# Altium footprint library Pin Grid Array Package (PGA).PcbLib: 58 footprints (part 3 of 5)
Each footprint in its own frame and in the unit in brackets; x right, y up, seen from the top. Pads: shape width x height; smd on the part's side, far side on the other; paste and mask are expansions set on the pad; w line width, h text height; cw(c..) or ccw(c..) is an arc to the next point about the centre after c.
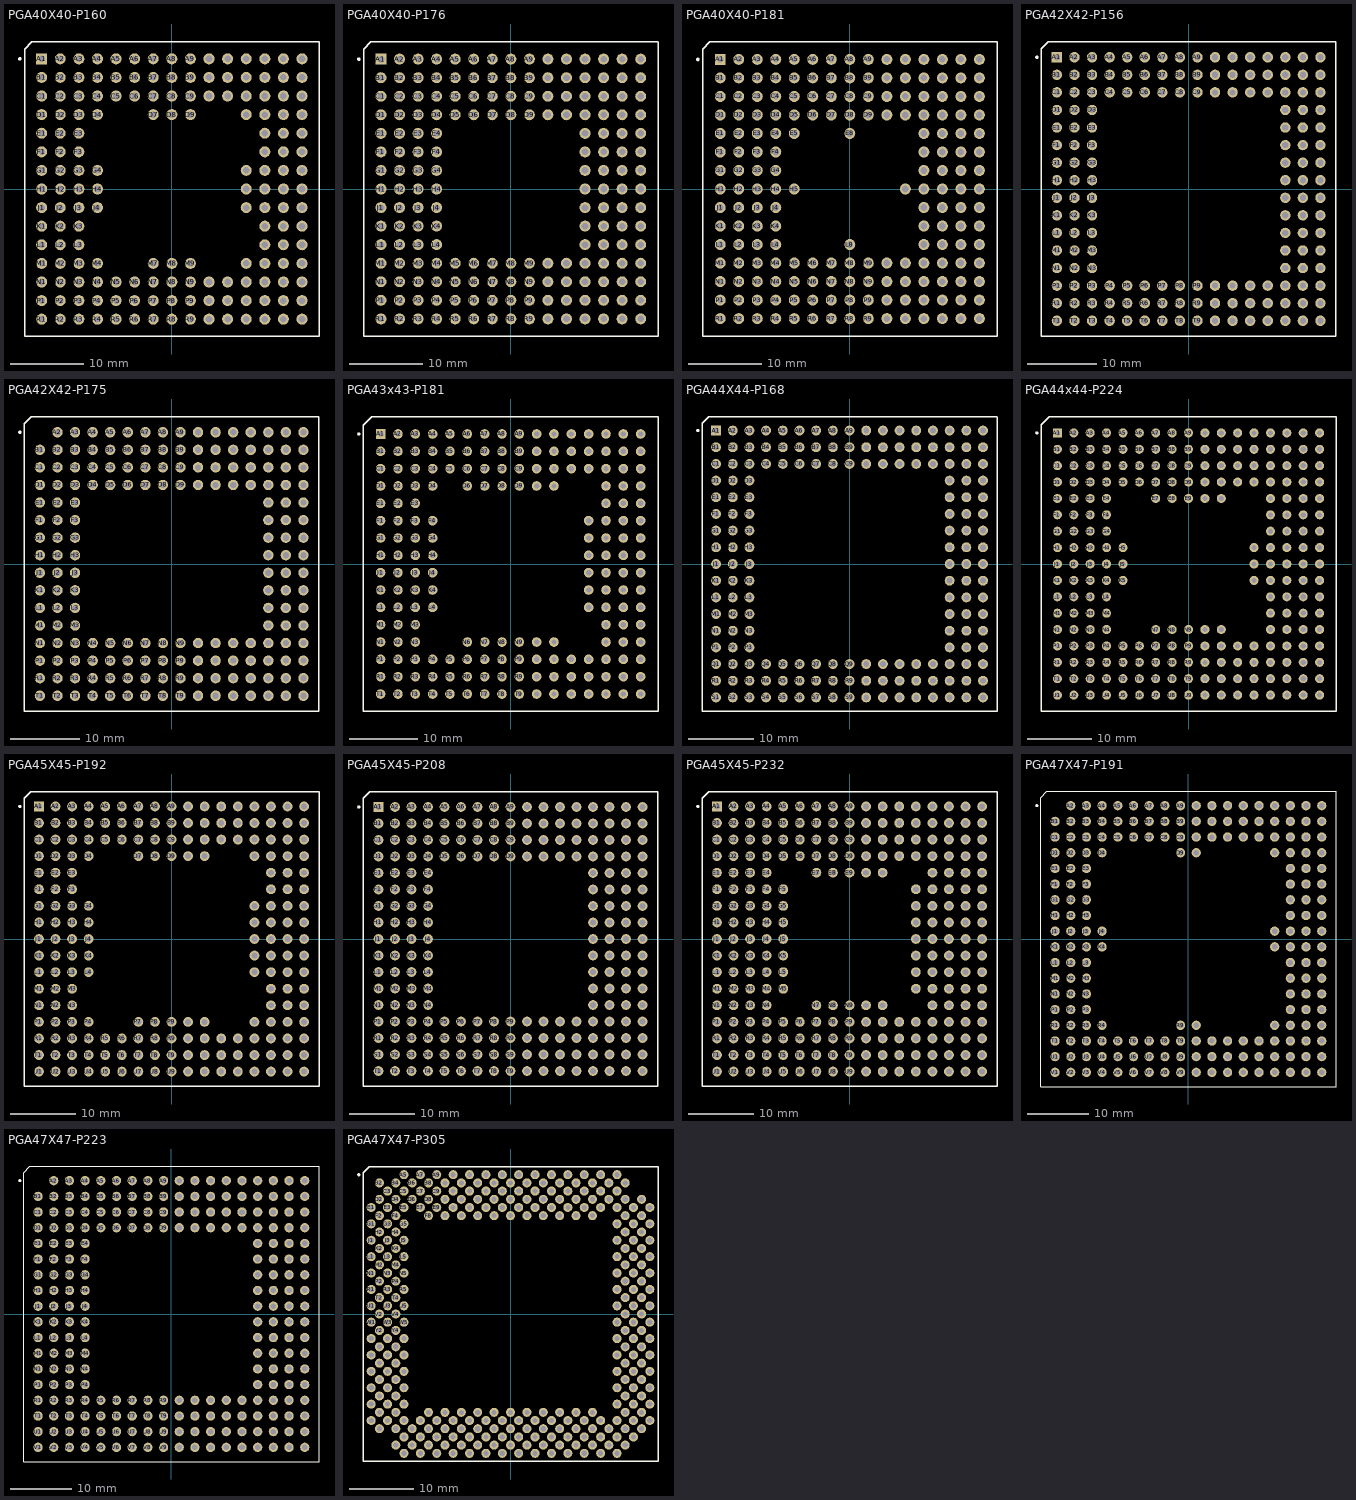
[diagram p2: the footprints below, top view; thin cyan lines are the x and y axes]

## PGA40X40-P160 [mm]
pads (160):
  rect 1.5x1.5 hole 0.9: A1(-17.78,17.78)
  round 1.5 hole 0.9: A2(-15.24,17.78) A3(-12.7,17.78) A4(-10.16,17.78) A5(-7.62,17.78) A6(-5.08,17.78) A7(-2.54,17.78) A8(0,17.78) A9(2.54,17.78) A10(5.08,17.78) A11(7.62,17.78) A12(10.16,17.78) A13(12.7,17.78) A14(15.24,17.78) A15(17.78,17.78) B1(-17.78,15.24) B2(-15.24,15.24) B3(-12.7,15.24) B4(-10.16,15.24) B5(-7.62,15.24) B6(-5.08,15.24) B7(-2.54,15.24) B8(0,15.24) B9(2.54,15.24) B10(5.08,15.24) B11(7.62,15.24) B12(10.16,15.24) B13(12.7,15.24) B14(15.24,15.24) B15(17.78,15.24) C1(-17.78,12.7) C2(-15.24,12.7) C3(-12.7,12.7) C4(-10.16,12.7) C5(-7.62,12.7) C6(-5.08,12.7) C7(-2.54,12.7) C8(0,12.7) C9(2.54,12.7) C10(5.08,12.7) C11(7.62,12.7) C12(10.16,12.7) C13(12.7,12.7) C14(15.24,12.7) C15(17.78,12.7) D1(-17.78,10.16) D2(-15.24,10.16) D3(-12.7,10.16) D4(-10.16,10.16) D7(-2.54,10.16) D8(0,10.16) D9(2.54,10.16) D12(10.16,10.16) D13(12.7,10.16) D14(15.24,10.16) D15(17.78,10.16) E1(-17.78,7.62) E2(-15.24,7.62) E3(-12.7,7.62) E13(12.7,7.62) E14(15.24,7.62) E15(17.78,7.62) F1(-17.78,5.08) F2(-15.24,5.08) F3(-12.7,5.08) F13(12.7,5.08) F14(15.24,5.08) F15(17.78,5.08) G1(-17.78,2.54) G2(-15.24,2.54) G3(-12.7,2.54) G4(-10.16,2.54) G12(10.16,2.54) G13(12.7,2.54) G14(15.24,2.54) G15(17.78,2.54) H1(-17.78,0) H2(-15.24,0) H3(-12.7,0) H4(-10.16,0) H12(10.16,0) H13(12.7,0) H14(15.24,0) H15(17.78,0) J1(-17.78,-2.54) J2(-15.24,-2.54) J3(-12.7,-2.54) J4(-10.16,-2.54) J12(10.16,-2.54) J13(12.7,-2.54) J14(15.24,-2.54) J15(17.78,-2.54) K1(-17.78,-5.08) K2(-15.24,-5.08) K3(-12.7,-5.08) K13(12.7,-5.08) K14(15.24,-5.08) K15(17.78,-5.08) L1(-17.78,-7.62) L2(-15.24,-7.62) L3(-12.7,-7.62) L13(12.7,-7.62) L14(15.24,-7.62) L15(17.78,-7.62) M1(-17.78,-10.16) M2(-15.24,-10.16) M3(-12.7,-10.16) M4(-10.16,-10.16) M7(-2.54,-10.16) M8(0,-10.16) M9(2.54,-10.16) M12(10.16,-10.16) M13(12.7,-10.16) M14(15.24,-10.16) M15(17.78,-10.16) N1(-17.78,-12.7) N2(-15.24,-12.7) N3(-12.7,-12.7) N4(-10.16,-12.7) N5(-7.62,-12.7) N6(-5.08,-12.7) N7(-2.54,-12.7) N8(0,-12.7) N9(2.54,-12.7) N10(5.08,-12.7) N11(7.62,-12.7) N12(10.16,-12.7) N13(12.7,-12.7) N14(15.24,-12.7) N15(17.78,-12.7) P1(-17.78,-15.24) P2(-15.24,-15.24) P3(-12.7,-15.24) P4(-10.16,-15.24) P5(-7.62,-15.24) P6(-5.08,-15.24) P7(-2.54,-15.24) P8(0,-15.24) P9(2.54,-15.24) P10(5.08,-15.24) P11(7.62,-15.24) P12(10.16,-15.24) P13(12.7,-15.24) P14(15.24,-15.24) P15(17.78,-15.24) R1(-17.78,-17.78) R2(-15.24,-17.78) R3(-12.7,-17.78) R4(-10.16,-17.78) R5(-7.62,-17.78) R6(-5.08,-17.78) R7(-2.54,-17.78) R8(0,-17.78) R9(2.54,-17.78) R10(5.08,-17.78) R11(7.62,-17.78) R12(10.16,-17.78) R13(12.7,-17.78) R14(15.24,-17.78) R15(17.78,-17.78)
Top Overlay:
  circle w0.25: c-20.75,17.78 r0.125
  lines w0.2: -20.1,-20.1 20.1,-20.1 20.1,20.1 -19.1,20.1 -20.1,19.1 -20.1,-20.1

## PGA40X40-P176 [mm]
pads (176):
  rect 1.5x1.5 hole 0.9: A1(-17.78,17.78)
  round 1.5 hole 0.9: A2(-15.24,17.78) A3(-12.7,17.78) A4(-10.16,17.78) A5(-7.62,17.78) A6(-5.08,17.78) A7(-2.54,17.78) A8(0,17.78) A9(2.54,17.78) A10(5.08,17.78) A11(7.62,17.78) A12(10.16,17.78) A13(12.7,17.78) A14(15.24,17.78) A15(17.78,17.78) B1(-17.78,15.24) B2(-15.24,15.24) B3(-12.7,15.24) B4(-10.16,15.24) B5(-7.62,15.24) B6(-5.08,15.24) B7(-2.54,15.24) B8(0,15.24) B9(2.54,15.24) B10(5.08,15.24) B11(7.62,15.24) B12(10.16,15.24) B13(12.7,15.24) B14(15.24,15.24) B15(17.78,15.24) C1(-17.78,12.7) C2(-15.24,12.7) C3(-12.7,12.7) C4(-10.16,12.7) C5(-7.62,12.7) C6(-5.08,12.7) C7(-2.54,12.7) C8(0,12.7) C9(2.54,12.7) C10(5.08,12.7) C11(7.62,12.7) C12(10.16,12.7) C13(12.7,12.7) C14(15.24,12.7) C15(17.78,12.7) D1(-17.78,10.16) D2(-15.24,10.16) D3(-12.7,10.16) D4(-10.16,10.16) D5(-7.62,10.16) D6(-5.08,10.16) D7(-2.54,10.16) D8(0,10.16) D9(2.54,10.16) D10(5.08,10.16) D11(7.62,10.16) D12(10.16,10.16) D13(12.7,10.16) D14(15.24,10.16) D15(17.78,10.16) E1(-17.78,7.62) E2(-15.24,7.62) E3(-12.7,7.62) E4(-10.16,7.62) E12(10.16,7.62) E13(12.7,7.62) E14(15.24,7.62) E15(17.78,7.62) F1(-17.78,5.08) F2(-15.24,5.08) F3(-12.7,5.08) F4(-10.16,5.08) F12(10.16,5.08) F13(12.7,5.08) F14(15.24,5.08) F15(17.78,5.08) G1(-17.78,2.54) G2(-15.24,2.54) G3(-12.7,2.54) G4(-10.16,2.54) G12(10.16,2.54) G13(12.7,2.54) G14(15.24,2.54) G15(17.78,2.54) H1(-17.78,0) H2(-15.24,0) H3(-12.7,0) H4(-10.16,0) H12(10.16,0) H13(12.7,0) H14(15.24,0) H15(17.78,0) J1(-17.78,-2.54) J2(-15.24,-2.54) J3(-12.7,-2.54) J4(-10.16,-2.54) J12(10.16,-2.54) J13(12.7,-2.54) J14(15.24,-2.54) J15(17.78,-2.54) K1(-17.78,-5.08) K2(-15.24,-5.08) K3(-12.7,-5.08) K4(-10.16,-5.08) K12(10.16,-5.08) K13(12.7,-5.08) K14(15.24,-5.08) K15(17.78,-5.08) L1(-17.78,-7.62) L2(-15.24,-7.62) L3(-12.7,-7.62) L4(-10.16,-7.62) L12(10.16,-7.62) L13(12.7,-7.62) L14(15.24,-7.62) L15(17.78,-7.62) M1(-17.78,-10.16) M2(-15.24,-10.16) M3(-12.7,-10.16) M4(-10.16,-10.16) M5(-7.62,-10.16) M6(-5.08,-10.16) M7(-2.54,-10.16) M8(0,-10.16) M9(2.54,-10.16) M10(5.08,-10.16) M11(7.62,-10.16) M12(10.16,-10.16) M13(12.7,-10.16) M14(15.24,-10.16) M15(17.78,-10.16) N1(-17.78,-12.7) N2(-15.24,-12.7) N3(-12.7,-12.7) N4(-10.16,-12.7) N5(-7.62,-12.7) N6(-5.08,-12.7) N7(-2.54,-12.7) N8(0,-12.7) N9(2.54,-12.7) N10(5.08,-12.7) N11(7.62,-12.7) N12(10.16,-12.7) N13(12.7,-12.7) N14(15.24,-12.7) N15(17.78,-12.7) P1(-17.78,-15.24) P2(-15.24,-15.24) P3(-12.7,-15.24) P4(-10.16,-15.24) P5(-7.62,-15.24) P6(-5.08,-15.24) P7(-2.54,-15.24) P8(0,-15.24) P9(2.54,-15.24) P10(5.08,-15.24) P11(7.62,-15.24) P12(10.16,-15.24) P13(12.7,-15.24) P14(15.24,-15.24) P15(17.78,-15.24) R1(-17.78,-17.78) R2(-15.24,-17.78) R3(-12.7,-17.78) R4(-10.16,-17.78) R5(-7.62,-17.78) R6(-5.08,-17.78) R7(-2.54,-17.78) R8(0,-17.78) R9(2.54,-17.78) R10(5.08,-17.78) R11(7.62,-17.78) R12(10.16,-17.78) R13(12.7,-17.78) R14(15.24,-17.78) R15(17.78,-17.78)
Top Overlay:
  circle w0.25: c-20.8,17.78 r0.125
  lines w0.2: -20.15,-20.15 20.15,-20.15 20.15,20.15 -19.15,20.15 -20.15,19.15 -20.15,-20.15

## PGA40X40-P181 [mm]
pads (181):
  rect 1.5x1.5 hole 0.9: A1(-17.78,17.78)
  round 1.5 hole 0.9: A2(-15.24,17.78) A3(-12.7,17.78) A4(-10.16,17.78) A5(-7.62,17.78) A6(-5.08,17.78) A7(-2.54,17.78) A8(0,17.78) A9(2.54,17.78) A10(5.08,17.78) A11(7.62,17.78) A12(10.16,17.78) A13(12.7,17.78) A14(15.24,17.78) A15(17.78,17.78) B1(-17.78,15.24) B2(-15.24,15.24) B3(-12.7,15.24) B4(-10.16,15.24) B5(-7.62,15.24) B6(-5.08,15.24) B7(-2.54,15.24) B8(0,15.24) B9(2.54,15.24) B10(5.08,15.24) B11(7.62,15.24) B12(10.16,15.24) B13(12.7,15.24) B14(15.24,15.24) B15(17.78,15.24) C1(-17.78,12.7) C2(-15.24,12.7) C3(-12.7,12.7) C4(-10.16,12.7) C5(-7.62,12.7) C6(-5.08,12.7) C7(-2.54,12.7) C8(0,12.7) C9(2.54,12.7) C10(5.08,12.7) C11(7.62,12.7) C12(10.16,12.7) C13(12.7,12.7) C14(15.24,12.7) C15(17.78,12.7) D1(-17.78,10.16) D2(-15.24,10.16) D3(-12.7,10.16) D4(-10.16,10.16) D5(-7.62,10.16) D6(-5.08,10.16) D7(-2.54,10.16) D8(0,10.16) D9(2.54,10.16) D10(5.08,10.16) D11(7.62,10.16) D12(10.16,10.16) D13(12.7,10.16) D14(15.24,10.16) D15(17.78,10.16) E1(-17.78,7.62) E2(-15.24,7.62) E3(-12.7,7.62) E4(-10.16,7.62) E5(-7.62,7.62) E8(0,7.62) E12(10.16,7.62) E13(12.7,7.62) E14(15.24,7.62) E15(17.78,7.62) F1(-17.78,5.08) F2(-15.24,5.08) F3(-12.7,5.08) F4(-10.16,5.08) F12(10.16,5.08) F13(12.7,5.08) F14(15.24,5.08) F15(17.78,5.08) G1(-17.78,2.54) G2(-15.24,2.54) G3(-12.7,2.54) G4(-10.16,2.54) G12(10.16,2.54) G13(12.7,2.54) G14(15.24,2.54) G15(17.78,2.54) H1(-17.78,0) H2(-15.24,0) H3(-12.7,0) H4(-10.16,0) H5(-7.62,0) H11(7.62,0) H12(10.16,0) H13(12.7,0) H14(15.24,0) H15(17.78,0) J1(-17.78,-2.54) J2(-15.24,-2.54) J3(-12.7,-2.54) J4(-10.16,-2.54) J12(10.16,-2.54) J13(12.7,-2.54) J14(15.24,-2.54) J15(17.78,-2.54) K1(-17.78,-5.08) K2(-15.24,-5.08) K3(-12.7,-5.08) K4(-10.16,-5.08) K12(10.16,-5.08) K13(12.7,-5.08) K14(15.24,-5.08) K15(17.78,-5.08) L1(-17.78,-7.62) L2(-15.24,-7.62) L3(-12.7,-7.62) L4(-10.16,-7.62) L8(0,-7.62) L12(10.16,-7.62) L13(12.7,-7.62) L14(15.24,-7.62) L15(17.78,-7.62) M1(-17.78,-10.16) M2(-15.24,-10.16) M3(-12.7,-10.16) M4(-10.16,-10.16) M5(-7.62,-10.16) M6(-5.08,-10.16) M7(-2.54,-10.16) M8(0,-10.16) M9(2.54,-10.16) M10(5.08,-10.16) M11(7.62,-10.16) M12(10.16,-10.16) M13(12.7,-10.16) M14(15.24,-10.16) M15(17.78,-10.16) N1(-17.78,-12.7) N2(-15.24,-12.7) N3(-12.7,-12.7) N4(-10.16,-12.7) N5(-7.62,-12.7) N6(-5.08,-12.7) N7(-2.54,-12.7) N8(0,-12.7) N9(2.54,-12.7) N10(5.08,-12.7) N11(7.62,-12.7) N12(10.16,-12.7) N13(12.7,-12.7) N14(15.24,-12.7) N15(17.78,-12.7) P1(-17.78,-15.24) P2(-15.24,-15.24) P3(-12.7,-15.24) P4(-10.16,-15.24) P5(-7.62,-15.24) P6(-5.08,-15.24) P7(-2.54,-15.24) P8(0,-15.24) P9(2.54,-15.24) P10(5.08,-15.24) P11(7.62,-15.24) P12(10.16,-15.24) P13(12.7,-15.24) P14(15.24,-15.24) P15(17.78,-15.24) R1(-17.78,-17.78) R2(-15.24,-17.78) R3(-12.7,-17.78) R4(-10.16,-17.78) R5(-7.62,-17.78) R6(-5.08,-17.78) R7(-2.54,-17.78) R8(0,-17.78) R9(2.54,-17.78) R10(5.08,-17.78) R11(7.62,-17.78) R12(10.16,-17.78) R13(12.7,-17.78) R14(15.24,-17.78) R15(17.78,-17.78)
Top Overlay:
  circle w0.25: c-20.85,17.78 r0.125
  lines w0.2: -20.2,-20.2 -20.2,19.2 -19.2,20.2 20.2,20.2 20.2,-20.2 -20.2,-20.2

## PGA42X42-P156 [mm]
pads (156):
  rect 1.5x1.5 hole 0.9: A1(-19.05,19.05)
  round 1.5 hole 0.9: A2(-16.51,19.05) A3(-13.97,19.05) A4(-11.43,19.05) A5(-8.89,19.05) A6(-6.35,19.05) A7(-3.81,19.05) A8(-1.27,19.05) A9(1.27,19.05) A10(3.81,19.05) A11(6.35,19.05) A12(8.89,19.05) A13(11.43,19.05) A14(13.97,19.05) A15(16.51,19.05) A16(19.05,19.05) B1(-19.05,16.51) B2(-16.51,16.51) B3(-13.97,16.51) B4(-11.43,16.51) B5(-8.89,16.51) B6(-6.35,16.51) B7(-3.81,16.51) B8(-1.27,16.51) B9(1.27,16.51) B10(3.81,16.51) B11(6.35,16.51) B12(8.89,16.51) B13(11.43,16.51) B14(13.97,16.51) B15(16.51,16.51) B16(19.05,16.51) C1(-19.05,13.97) C2(-16.51,13.97) C3(-13.97,13.97) C4(-11.43,13.97) C5(-8.89,13.97) C6(-6.35,13.97) C7(-3.81,13.97) C8(-1.27,13.97) C9(1.27,13.97) C10(3.81,13.97) C11(6.35,13.97) C12(8.89,13.97) C13(11.43,13.97) C14(13.97,13.97) C15(16.51,13.97) C16(19.05,13.97) D1(-19.05,11.43) D2(-16.51,11.43) D3(-13.97,11.43) D14(13.97,11.43) D15(16.51,11.43) D16(19.05,11.43) E1(-19.05,8.89) E2(-16.51,8.89) E3(-13.97,8.89) E14(13.97,8.89) E15(16.51,8.89) E16(19.05,8.89) F1(-19.05,6.35) F2(-16.51,6.35) F3(-13.97,6.35) F14(13.97,6.35) F15(16.51,6.35) F16(19.05,6.35) G1(-19.05,3.81) G2(-16.51,3.81) G3(-13.97,3.81) G14(13.97,3.81) G15(16.51,3.81) G16(19.05,3.81) H1(-19.05,1.27) H2(-16.51,1.27) H3(-13.97,1.27) H14(13.97,1.27) H15(16.51,1.27) H16(19.05,1.27) J1(-19.05,-1.27) J2(-16.51,-1.27) J3(-13.97,-1.27) J14(13.97,-1.27) J15(16.51,-1.27) J16(19.05,-1.27) K1(-19.05,-3.81) K2(-16.51,-3.81) K3(-13.97,-3.81) K14(13.97,-3.81) K15(16.51,-3.81) K16(19.05,-3.81) L1(-19.05,-6.35) L2(-16.51,-6.35) L3(-13.97,-6.35) L14(13.97,-6.35) L15(16.51,-6.35) L16(19.05,-6.35) M1(-19.05,-8.89) M2(-16.51,-8.89) M3(-13.97,-8.89) M14(13.97,-8.89) M15(16.51,-8.89) M16(19.05,-8.89) N1(-19.05,-11.43) N2(-16.51,-11.43) N3(-13.97,-11.43) N14(13.97,-11.43) N15(16.51,-11.43) N16(19.05,-11.43) P1(-19.05,-13.97) P2(-16.51,-13.97) P3(-13.97,-13.97) P4(-11.43,-13.97) P5(-8.89,-13.97) P6(-6.35,-13.97) P7(-3.81,-13.97) P8(-1.27,-13.97) P9(1.27,-13.97) P10(3.81,-13.97) P11(6.35,-13.97) P12(8.89,-13.97) P13(11.43,-13.97) P14(13.97,-13.97) P15(16.51,-13.97) P16(19.05,-13.97) R1(-19.05,-16.51) R2(-16.51,-16.51) R3(-13.97,-16.51) R4(-11.43,-16.51) R5(-8.89,-16.51) R6(-6.35,-16.51) R7(-3.81,-16.51) R8(-1.27,-16.51) R9(1.27,-16.51) R10(3.81,-16.51) R11(6.35,-16.51) R12(8.89,-16.51) R13(11.43,-16.51) R14(13.97,-16.51) R15(16.51,-16.51) R16(19.05,-16.51) T1(-19.05,-19.05) T2(-16.51,-19.05) T3(-13.97,-19.05) T4(-11.43,-19.05) T5(-8.89,-19.05) T6(-6.35,-19.05) T7(-3.81,-19.05) T8(-1.27,-19.05) T9(1.27,-19.05) T10(3.81,-19.05) T11(6.35,-19.05) T12(8.89,-19.05) T13(11.43,-19.05) T14(13.97,-19.05) T15(16.51,-19.05) T16(19.05,-19.05)
Top Overlay:
  circle w0.25: c-21.95,19.05 r0.125
  lines w0.2: -21.3,-21.3 -21.3,20.3 -20.3,21.3 21.3,21.3 21.3,-21.3 -21.3,-21.3

## PGA42X42-P175 [mm]
pads (175):
  round 1.5 hole 0.9: A2(-16.51,19.05) A3(-13.97,19.05) A4(-11.43,19.05) A5(-8.89,19.05) A6(-6.35,19.05) A7(-3.81,19.05) A8(-1.27,19.05) A9(1.27,19.05) A10(3.81,19.05) A11(6.35,19.05) A12(8.89,19.05) A13(11.43,19.05) A14(13.97,19.05) A15(16.51,19.05) A16(19.05,19.05) B1(-19.05,16.51) B2(-16.51,16.51) B3(-13.97,16.51) B4(-11.43,16.51) B5(-8.89,16.51) B6(-6.35,16.51) B7(-3.81,16.51) B8(-1.27,16.51) B9(1.27,16.51) B10(3.81,16.51) B11(6.35,16.51) B12(8.89,16.51) B13(11.43,16.51) B14(13.97,16.51) B15(16.51,16.51) B16(19.05,16.51) C1(-19.05,13.97) C2(-16.51,13.97) C3(-13.97,13.97) C4(-11.43,13.97) C5(-8.89,13.97) C6(-6.35,13.97) C7(-3.81,13.97) C8(-1.27,13.97) C9(1.27,13.97) C10(3.81,13.97) C11(6.35,13.97) C12(8.89,13.97) C13(11.43,13.97) C14(13.97,13.97) C15(16.51,13.97) C16(19.05,13.97) D1(-19.05,11.43) D2(-16.51,11.43) D3(-13.97,11.43) D4(-11.43,11.43) D5(-8.89,11.43) D6(-6.35,11.43) D7(-3.81,11.43) D8(-1.27,11.43) D9(1.27,11.43) D10(3.81,11.43) D11(6.35,11.43) D12(8.89,11.43) D13(11.43,11.43) D14(13.97,11.43) D15(16.51,11.43) D16(19.05,11.43) E1(-19.05,8.89) E2(-16.51,8.89) E3(-13.97,8.89) E14(13.97,8.89) E15(16.51,8.89) E16(19.05,8.89) F1(-19.05,6.35) F2(-16.51,6.35) F3(-13.97,6.35) F14(13.97,6.35) F15(16.51,6.35) F16(19.05,6.35) G1(-19.05,3.81) G2(-16.51,3.81) G3(-13.97,3.81) G14(13.97,3.81) G15(16.51,3.81) G16(19.05,3.81) H1(-19.05,1.27) H2(-16.51,1.27) H3(-13.97,1.27) H14(13.97,1.27) H15(16.51,1.27) H16(19.05,1.27) J1(-19.05,-1.27) J2(-16.51,-1.27) J3(-13.97,-1.27) J14(13.97,-1.27) J15(16.51,-1.27) J16(19.05,-1.27) K1(-19.05,-3.81) K2(-16.51,-3.81) K3(-13.97,-3.81) K14(13.97,-3.81) K15(16.51,-3.81) K16(19.05,-3.81) L1(-19.05,-6.35) L2(-16.51,-6.35) L3(-13.97,-6.35) L14(13.97,-6.35) L15(16.51,-6.35) L16(19.05,-6.35) M1(-19.05,-8.89) M2(-16.51,-8.89) M3(-13.97,-8.89) M14(13.97,-8.89) M15(16.51,-8.89) M16(19.05,-8.89) N1(-19.05,-11.43) N2(-16.51,-11.43) N3(-13.97,-11.43) N4(-11.43,-11.43) N5(-8.89,-11.43) N6(-6.35,-11.43) N7(-3.81,-11.43) N8(-1.27,-11.43) N9(1.27,-11.43) N10(3.81,-11.43) N11(6.35,-11.43) N12(8.89,-11.43) N13(11.43,-11.43) N14(13.97,-11.43) N15(16.51,-11.43) N16(19.05,-11.43) P1(-19.05,-13.97) P2(-16.51,-13.97) P3(-13.97,-13.97) P4(-11.43,-13.97) P5(-8.89,-13.97) P6(-6.35,-13.97) P7(-3.81,-13.97) P8(-1.27,-13.97) P9(1.27,-13.97) P10(3.81,-13.97) P11(6.35,-13.97) P12(8.89,-13.97) P13(11.43,-13.97) P14(13.97,-13.97) P15(16.51,-13.97) P16(19.05,-13.97) R1(-19.05,-16.51) R2(-16.51,-16.51) R3(-13.97,-16.51) R4(-11.43,-16.51) R5(-8.89,-16.51) R6(-6.35,-16.51) R7(-3.81,-16.51) R8(-1.27,-16.51) R9(1.27,-16.51) R10(3.81,-16.51) R11(6.35,-16.51) R12(8.89,-16.51) R13(11.43,-16.51) R14(13.97,-16.51) R15(16.51,-16.51) R16(19.05,-16.51) T1(-19.05,-19.05) T2(-16.51,-19.05) T3(-13.97,-19.05) T4(-11.43,-19.05) T5(-8.89,-19.05) T6(-6.35,-19.05) T7(-3.81,-19.05) T8(-1.27,-19.05) T9(1.27,-19.05) T10(3.81,-19.05) T11(6.35,-19.05) T12(8.89,-19.05) T13(11.43,-19.05) T14(13.97,-19.05) T15(16.51,-19.05) T16(19.05,-19.05)
Top Overlay:
  circle w0.25: c-21.95,19.05 r0.125
  lines w0.2: -21.3,-21.3 21.3,-21.3 21.3,21.3 -20.3,21.3 -21.3,20.3 -21.3,-21.3

## PGA43x43-P181 [mm]
pads (181):
  rect 1.4x1.4 hole 0.8: A1(-19.05,19.05)
  round 1.4 hole 0.8: A2(-16.51,19.05) A3(-13.97,19.05) A4(-11.43,19.05) A5(-8.89,19.05) A6(-6.35,19.05) A7(-3.81,19.05) A8(-1.27,19.05) A9(1.27,19.05) A10(3.81,19.05) A11(6.35,19.05) A12(8.89,19.05) A13(11.43,19.05) A14(13.97,19.05) A15(16.51,19.05) A16(19.05,19.05) B1(-19.05,16.51) B2(-16.51,16.51) B3(-13.97,16.51) B4(-11.43,16.51) B5(-8.89,16.51) B6(-6.35,16.51) B7(-3.81,16.51) B8(-1.27,16.51) B9(1.27,16.51) B10(3.81,16.51) B11(6.35,16.51) B12(8.89,16.51) B13(11.43,16.51) B14(13.97,16.51) B15(16.51,16.51) B16(19.05,16.51) C1(-19.05,13.97) C2(-16.51,13.97) C3(-13.97,13.97) C4(-11.43,13.97) C5(-8.89,13.97) C6(-6.35,13.97) C7(-3.81,13.97) C8(-1.27,13.97) C9(1.27,13.97) C10(3.81,13.97) C11(6.35,13.97) C12(8.89,13.97) C13(11.43,13.97) C14(13.97,13.97) C15(16.51,13.97) C16(19.05,13.97) D1(-19.05,11.43) D2(-16.51,11.43) D3(-13.97,11.43) D4(-11.43,11.43) D6(-6.35,11.43) D7(-3.81,11.43) D8(-1.27,11.43) D9(1.27,11.43) D10(3.81,11.43) D11(6.35,11.43) D14(13.97,11.43) D15(16.51,11.43) D16(19.05,11.43) E1(-19.05,8.89) E2(-16.51,8.89) E3(-13.97,8.89) E14(13.97,8.89) E15(16.51,8.89) E16(19.05,8.89) F1(-19.05,6.35) F2(-16.51,6.35) F3(-13.97,6.35) F4(-11.43,6.35) F13(11.43,6.35) F14(13.97,6.35) F15(16.51,6.35) F16(19.05,6.35) G1(-19.05,3.81) G2(-16.51,3.81) G3(-13.97,3.81) G4(-11.43,3.81) G13(11.43,3.81) G14(13.97,3.81) G15(16.51,3.81) G16(19.05,3.81) H1(-19.05,1.27) H2(-16.51,1.27) H3(-13.97,1.27) H4(-11.43,1.27) H13(11.43,1.27) H14(13.97,1.27) H15(16.51,1.27) H16(19.05,1.27) J1(-19.05,-1.27) J2(-16.51,-1.27) J3(-13.97,-1.27) J4(-11.43,-1.27) J13(11.43,-1.27) J14(13.97,-1.27) J15(16.51,-1.27) J16(19.05,-1.27) K1(-19.05,-3.81) K2(-16.51,-3.81) K3(-13.97,-3.81) K4(-11.43,-3.81) K13(11.43,-3.81) K14(13.97,-3.81) K15(16.51,-3.81) K16(19.05,-3.81) L1(-19.05,-6.35) L2(-16.51,-6.35) L3(-13.97,-6.35) L4(-11.43,-6.35) L13(11.43,-6.35) L14(13.97,-6.35) L15(16.51,-6.35) L16(19.05,-6.35) M1(-19.05,-8.89) M2(-16.51,-8.89) M3(-13.97,-8.89) M14(13.97,-8.89) M15(16.51,-8.89) M16(19.05,-8.89) N1(-19.05,-11.43) N2(-16.51,-11.43) N3(-13.97,-11.43) N6(-6.35,-11.43) N7(-3.81,-11.43) N8(-1.27,-11.43) N9(1.27,-11.43) N10(3.81,-11.43) N11(6.35,-11.43) N14(13.97,-11.43) N15(16.51,-11.43) N16(19.05,-11.43) P1(-19.05,-13.97) P2(-16.51,-13.97) P3(-13.97,-13.97) P4(-11.43,-13.97) P5(-8.89,-13.97) P6(-6.35,-13.97) P7(-3.81,-13.97) P8(-1.27,-13.97) P9(1.27,-13.97) P10(3.81,-13.97) P11(6.35,-13.97) P12(8.89,-13.97) P13(11.43,-13.97) P14(13.97,-13.97) P15(16.51,-13.97) P16(19.05,-13.97) R1(-19.05,-16.51) R2(-16.51,-16.51) R3(-13.97,-16.51) R4(-11.43,-16.51) R5(-8.89,-16.51) R6(-6.35,-16.51) R7(-3.81,-16.51) R8(-1.27,-16.51) R9(1.27,-16.51) R10(3.81,-16.51) R11(6.35,-16.51) R12(8.89,-16.51) R13(11.43,-16.51) R14(13.97,-16.51) R15(16.51,-16.51) R16(19.05,-16.51) T1(-19.05,-19.05) T2(-16.51,-19.05) T3(-13.97,-19.05) T4(-11.43,-19.05) T5(-8.89,-19.05) T6(-6.35,-19.05) T7(-3.81,-19.05) T8(-1.27,-19.05) T9(1.27,-19.05) T10(3.81,-19.05) T11(6.35,-19.05) T12(8.89,-19.05) T13(11.43,-19.05) T14(13.97,-19.05) T15(16.51,-19.05) T16(19.05,-19.05)
Top Overlay:
  circle w0.25: c-22.24,19.05 r0.125
  lines w0.2: -21.59,-21.59 21.59,-21.59 21.59,21.59 -20.32,21.59 -21.59,20.32 -21.59,-21.59

## PGA44X44-P168 [mm]
pads (168):
  rect 1.5x1.5 hole 0.9: A1(-20.32,20.32)
  round 1.5 hole 0.9: A2(-17.78,20.32) A3(-15.24,20.32) A4(-12.7,20.32) A5(-10.16,20.32) A6(-7.62,20.32) A7(-5.08,20.32) A8(-2.54,20.32) A9(0,20.32) A10(2.54,20.32) A11(5.08,20.32) A12(7.62,20.32) A13(10.16,20.32) A14(12.7,20.32) A15(15.24,20.32) A16(17.78,20.32) A17(20.32,20.32) B1(-20.32,17.78) B2(-17.78,17.78) B3(-15.24,17.78) B4(-12.7,17.78) B5(-10.16,17.78) B6(-7.62,17.78) B7(-5.08,17.78) B8(-2.54,17.78) B9(0,17.78) B10(2.54,17.78) B11(5.08,17.78) B12(7.62,17.78) B13(10.16,17.78) B14(12.7,17.78) B15(15.24,17.78) B16(17.78,17.78) B17(20.32,17.78) C1(-20.32,15.24) C2(-17.78,15.24) C3(-15.24,15.24) C4(-12.7,15.24) C5(-10.16,15.24) C6(-7.62,15.24) C7(-5.08,15.24) C8(-2.54,15.24) C9(0,15.24) C10(2.54,15.24) C11(5.08,15.24) C12(7.62,15.24) C13(10.16,15.24) C14(12.7,15.24) C15(15.24,15.24) C16(17.78,15.24) C17(20.32,15.24) D1(-20.32,12.7) D2(-17.78,12.7) D3(-15.24,12.7) D15(15.24,12.7) D16(17.78,12.7) D17(20.32,12.7) E1(-20.32,10.16) E2(-17.78,10.16) E3(-15.24,10.16) E15(15.24,10.16) E16(17.78,10.16) E17(20.32,10.16) F1(-20.32,7.62) F2(-17.78,7.62) F3(-15.24,7.62) F15(15.24,7.62) F16(17.78,7.62) F17(20.32,7.62) G1(-20.32,5.08) G2(-17.78,5.08) G3(-15.24,5.08) G15(15.24,5.08) G16(17.78,5.08) G17(20.32,5.08) H1(-20.32,2.54) H2(-17.78,2.54) H3(-15.24,2.54) H15(15.24,2.54) H16(17.78,2.54) H17(20.32,2.54) J1(-20.32,0) J2(-17.78,0) J3(-15.24,0) J15(15.24,0) J16(17.78,0) J17(20.32,0) K1(-20.32,-2.54) K2(-17.78,-2.54) K3(-15.24,-2.54) K15(15.24,-2.54) K16(17.78,-2.54) K17(20.32,-2.54) L1(-20.32,-5.08) L2(-17.78,-5.08) L3(-15.24,-5.08) L15(15.24,-5.08) L16(17.78,-5.08) L17(20.32,-5.08) M1(-20.32,-7.62) M2(-17.78,-7.62) M3(-15.24,-7.62) M15(15.24,-7.62) M16(17.78,-7.62) M17(20.32,-7.62) N1(-20.32,-10.16) N2(-17.78,-10.16) N3(-15.24,-10.16) N15(15.24,-10.16) N16(17.78,-10.16) N17(20.32,-10.16) P1(-20.32,-12.7) P2(-17.78,-12.7) P3(-15.24,-12.7) P15(15.24,-12.7) P16(17.78,-12.7) P17(20.32,-12.7) Q1(-20.32,-15.24) Q2(-17.78,-15.24) Q3(-15.24,-15.24) Q4(-12.7,-15.24) Q5(-10.16,-15.24) Q6(-7.62,-15.24) Q7(-5.08,-15.24) Q8(-2.54,-15.24) Q9(0,-15.24) Q10(2.54,-15.24) Q11(5.08,-15.24) Q12(7.62,-15.24) Q13(10.16,-15.24) Q14(12.7,-15.24) Q15(15.24,-15.24) Q16(17.78,-15.24) Q17(20.32,-15.24) R1(-20.32,-17.78) R2(-17.78,-17.78) R3(-15.24,-17.78) R4(-12.7,-17.78) R5(-10.16,-17.78) R6(-7.62,-17.78) R7(-5.08,-17.78) R8(-2.54,-17.78) R9(0,-17.78) R10(2.54,-17.78) R11(5.08,-17.78) R12(7.62,-17.78) R13(10.16,-17.78) R14(12.7,-17.78) R15(15.24,-17.78) R16(17.78,-17.78) R17(20.32,-17.78) S1(-20.32,-20.32) S2(-17.78,-20.32) S3(-15.24,-20.32) S4(-12.7,-20.32) S5(-10.16,-20.32) S6(-7.62,-20.32) S7(-5.08,-20.32) S8(-2.54,-20.32) S9(0,-20.32) S10(2.54,-20.32) S11(5.08,-20.32) S12(7.62,-20.32) S13(10.16,-20.32) S14(12.7,-20.32) S15(15.24,-20.32) S16(17.78,-20.32) S17(20.32,-20.32)
Top Overlay:
  circle w0.25: c-23.1,20.32 r0.125
  lines w0.2: -22.45,-22.45 -22.45,21.45 -21.45,22.45 22.45,22.45 22.45,-22.45 -22.45,-22.45

## PGA44x44-P224 [mm]
pads (224):
  rect 1.4x1.4 hole 0.8: A1(-20.32,20.32)
  round 1.4 hole 0.8: A2(-17.78,20.32) A3(-15.24,20.32) A4(-12.7,20.32) A5(-10.16,20.32) A6(-7.62,20.32) A7(-5.08,20.32) A8(-2.54,20.32) A9(0,20.32) A10(2.54,20.32) A11(5.08,20.32) A12(7.62,20.32) A13(10.16,20.32) A14(12.7,20.32) A15(15.24,20.32) A16(17.78,20.32) A17(20.32,20.32) B1(-20.32,17.78) B2(-17.78,17.78) B3(-15.24,17.78) B4(-12.7,17.78) B5(-10.16,17.78) B6(-7.62,17.78) B7(-5.08,17.78) B8(-2.54,17.78) B9(0,17.78) B10(2.54,17.78) B11(5.08,17.78) B12(7.62,17.78) B13(10.16,17.78) B14(12.7,17.78) B15(15.24,17.78) B16(17.78,17.78) B17(20.32,17.78) C1(-20.32,15.24) C2(-17.78,15.24) C3(-15.24,15.24) C4(-12.7,15.24) C5(-10.16,15.24) C6(-7.62,15.24) C7(-5.08,15.24) C8(-2.54,15.24) C9(0,15.24) C10(2.54,15.24) C11(5.08,15.24) C12(7.62,15.24) C13(10.16,15.24) C14(12.7,15.24) C15(15.24,15.24) C16(17.78,15.24) C17(20.32,15.24) D1(-20.32,12.7) D2(-17.78,12.7) D3(-15.24,12.7) D4(-12.7,12.7) D5(-10.16,12.7) D6(-7.62,12.7) D7(-5.08,12.7) D8(-2.54,12.7) D9(0,12.7) D10(2.54,12.7) D11(5.08,12.7) D12(7.62,12.7) D13(10.16,12.7) D14(12.7,12.7) D15(15.24,12.7) D16(17.78,12.7) D17(20.32,12.7) E1(-20.32,10.16) E2(-17.78,10.16) E3(-15.24,10.16) E4(-12.7,10.16) E7(-5.08,10.16) E8(-2.54,10.16) E9(0,10.16) E10(2.54,10.16) E11(5.08,10.16) E14(12.7,10.16) E15(15.24,10.16) E16(17.78,10.16) E17(20.32,10.16) F1(-20.32,7.62) F2(-17.78,7.62) F3(-15.24,7.62) F4(-12.7,7.62) F14(12.7,7.62) F15(15.24,7.62) F16(17.78,7.62) F17(20.32,7.62) G1(-20.32,5.08) G2(-17.78,5.08) G3(-15.24,5.08) G4(-12.7,5.08) G14(12.7,5.08) G15(15.24,5.08) G16(17.78,5.08) G17(20.32,5.08) H1(-20.32,2.54) H2(-17.78,2.54) H3(-15.24,2.54) H4(-12.7,2.54) H5(-10.16,2.54) H13(10.16,2.54) H14(12.7,2.54) H15(15.24,2.54) H16(17.78,2.54) H17(20.32,2.54) J1(-20.32,0) J2(-17.78,0) J3(-15.24,0) J4(-12.7,0) J5(-10.16,0) J13(10.16,0) J14(12.7,0) J15(15.24,0) J16(17.78,0) J17(20.32,0) K1(-20.32,-2.54) K2(-17.78,-2.54) K3(-15.24,-2.54) K4(-12.7,-2.54) K5(-10.16,-2.54) K13(10.16,-2.54) K14(12.7,-2.54) K15(15.24,-2.54) K16(17.78,-2.54) K17(20.32,-2.54) L1(-20.32,-5.08) L2(-17.78,-5.08) L3(-15.24,-5.08) L4(-12.7,-5.08) L14(12.7,-5.08) L15(15.24,-5.08) L16(17.78,-5.08) L17(20.32,-5.08) M1(-20.32,-7.62) M2(-17.78,-7.62) M3(-15.24,-7.62) M4(-12.7,-7.62) M14(12.7,-7.62) M15(15.24,-7.62) M16(17.78,-7.62) M17(20.32,-7.62) N1(-20.32,-10.16) N2(-17.78,-10.16) N3(-15.24,-10.16) N4(-12.7,-10.16) N7(-5.08,-10.16) N8(-2.54,-10.16) N9(0,-10.16) N10(2.54,-10.16) N11(5.08,-10.16) N14(12.7,-10.16) N15(15.24,-10.16) N16(17.78,-10.16) N17(20.32,-10.16) P1(-20.32,-12.7) P2(-17.78,-12.7) P3(-15.24,-12.7) P4(-12.7,-12.7) P5(-10.16,-12.7) P6(-7.62,-12.7) P7(-5.08,-12.7) P8(-2.54,-12.7) P9(0,-12.7) P10(2.54,-12.7) P11(5.08,-12.7) P12(7.62,-12.7) P13(10.16,-12.7) P14(12.7,-12.7) P15(15.24,-12.7) P16(17.78,-12.7) P17(20.32,-12.7) R1(-20.32,-15.24) R2(-17.78,-15.24) R3(-15.24,-15.24) R4(-12.7,-15.24) R5(-10.16,-15.24) R6(-7.62,-15.24) R7(-5.08,-15.24) R8(-2.54,-15.24) R9(0,-15.24) R10(2.54,-15.24) R11(5.08,-15.24) R12(7.62,-15.24) R13(10.16,-15.24) R14(12.7,-15.24) R15(15.24,-15.24) R16(17.78,-15.24) R17(20.32,-15.24) T1(-20.32,-17.78) T2(-17.78,-17.78) T3(-15.24,-17.78) T4(-12.7,-17.78) T5(-10.16,-17.78) T6(-7.62,-17.78) T7(-5.08,-17.78) T8(-2.54,-17.78) T9(0,-17.78) T10(2.54,-17.78) T11(5.08,-17.78) T12(7.62,-17.78) T13(10.16,-17.78) T14(12.7,-17.78) T15(15.24,-17.78) T16(17.78,-17.78) T17(20.32,-17.78) U1(-20.32,-20.32) U2(-17.78,-20.32) U3(-15.24,-20.32) U4(-12.7,-20.32) U5(-10.16,-20.32) U6(-7.62,-20.32) U7(-5.08,-20.32) U8(-2.54,-20.32) U9(0,-20.32) U10(2.54,-20.32) U11(5.08,-20.32) U12(7.62,-20.32) U13(10.16,-20.32) U14(12.7,-20.32) U15(15.24,-20.32) U16(17.78,-20.32) U17(20.32,-20.32)
Top Overlay:
  circle w0.25: c-23.51,20.32 r0.125
  lines w0.2: -22.86,-22.86 -22.86,21.59 -21.59,22.86 22.86,22.86 22.86,-22.86 -22.86,-22.86

## PGA45X45-P192 [mm]
pads (192):
  rect 1.5x1.5 hole 0.9: A1(-20.32,20.32)
  round 1.5 hole 0.9: A2(-17.78,20.32) A3(-15.24,20.32) A4(-12.7,20.32) A5(-10.16,20.32) A6(-7.62,20.32) A7(-5.08,20.32) A8(-2.54,20.32) A9(0,20.32) A10(2.54,20.32) A11(5.08,20.32) A12(7.62,20.32) A13(10.16,20.32) A14(12.7,20.32) A15(15.24,20.32) A16(17.78,20.32) A17(20.32,20.32) B1(-20.32,17.78) B2(-17.78,17.78) B3(-15.24,17.78) B4(-12.7,17.78) B5(-10.16,17.78) B6(-7.62,17.78) B7(-5.08,17.78) B8(-2.54,17.78) B9(0,17.78) B10(2.54,17.78) B11(5.08,17.78) B12(7.62,17.78) B13(10.16,17.78) B14(12.7,17.78) B15(15.24,17.78) B16(17.78,17.78) B17(20.32,17.78) C1(-20.32,15.24) C2(-17.78,15.24) C3(-15.24,15.24) C4(-12.7,15.24) C5(-10.16,15.24) C6(-7.62,15.24) C7(-5.08,15.24) C8(-2.54,15.24) C9(0,15.24) C10(2.54,15.24) C11(5.08,15.24) C12(7.62,15.24) C13(10.16,15.24) C14(12.7,15.24) C15(15.24,15.24) C16(17.78,15.24) C17(20.32,15.24) D1(-20.32,12.7) D2(-17.78,12.7) D3(-15.24,12.7) D4(-12.7,12.7) D7(-5.08,12.7) D8(-2.54,12.7) D9(0,12.7) D10(2.54,12.7) D11(5.08,12.7) D14(12.7,12.7) D15(15.24,12.7) D16(17.78,12.7) D17(20.32,12.7) E1(-20.32,10.16) E2(-17.78,10.16) E3(-15.24,10.16) E15(15.24,10.16) E16(17.78,10.16) E17(20.32,10.16) F1(-20.32,7.62) F2(-17.78,7.62) F3(-15.24,7.62) F15(15.24,7.62) F16(17.78,7.62) F17(20.32,7.62) G1(-20.32,5.08) G2(-17.78,5.08) G3(-15.24,5.08) G4(-12.7,5.08) G14(12.7,5.08) G15(15.24,5.08) G16(17.78,5.08) G17(20.32,5.08) H1(-20.32,2.54) H2(-17.78,2.54) H3(-15.24,2.54) H4(-12.7,2.54) H14(12.7,2.54) H15(15.24,2.54) H16(17.78,2.54) H17(20.32,2.54) J1(-20.32,0) J2(-17.78,0) J3(-15.24,0) J4(-12.7,0) J14(12.7,0) J15(15.24,0) J16(17.78,0) J17(20.32,0) K1(-20.32,-2.54) K2(-17.78,-2.54) K3(-15.24,-2.54) K4(-12.7,-2.54) K14(12.7,-2.54) K15(15.24,-2.54) K16(17.78,-2.54) K17(20.32,-2.54) L1(-20.32,-5.08) L2(-17.78,-5.08) L3(-15.24,-5.08) L4(-12.7,-5.08) L14(12.7,-5.08) L15(15.24,-5.08) L16(17.78,-5.08) L17(20.32,-5.08) M1(-20.32,-7.62) M2(-17.78,-7.62) M3(-15.24,-7.62) M15(15.24,-7.62) M16(17.78,-7.62) M17(20.32,-7.62) N1(-20.32,-10.16) N2(-17.78,-10.16) N3(-15.24,-10.16) N15(15.24,-10.16) N16(17.78,-10.16) N17(20.32,-10.16) P1(-20.32,-12.7) P2(-17.78,-12.7) P3(-15.24,-12.7) P4(-12.7,-12.7) P7(-5.08,-12.7) P8(-2.54,-12.7) P9(0,-12.7) P10(2.54,-12.7) P11(5.08,-12.7) P14(12.7,-12.7) P15(15.24,-12.7) P16(17.78,-12.7) P17(20.32,-12.7) R1(-20.32,-15.24) R2(-17.78,-15.24) R3(-15.24,-15.24) R4(-12.7,-15.24) R5(-10.16,-15.24) R6(-7.62,-15.24) R7(-5.08,-15.24) R8(-2.54,-15.24) R9(0,-15.24) R10(2.54,-15.24) R11(5.08,-15.24) R12(7.62,-15.24) R13(10.16,-15.24) R14(12.7,-15.24) R15(15.24,-15.24) R16(17.78,-15.24) R17(20.32,-15.24) T1(-20.32,-17.78) T2(-17.78,-17.78) T3(-15.24,-17.78) T4(-12.7,-17.78) T5(-10.16,-17.78) T6(-7.62,-17.78) T7(-5.08,-17.78) T8(-2.54,-17.78) T9(0,-17.78) T10(2.54,-17.78) T11(5.08,-17.78) T12(7.62,-17.78) T13(10.16,-17.78) T14(12.7,-17.78) T15(15.24,-17.78) T16(17.78,-17.78) T17(20.32,-17.78) U1(-20.32,-20.32) U2(-17.78,-20.32) U3(-15.24,-20.32) U4(-12.7,-20.32) U5(-10.16,-20.32) U6(-7.62,-20.32) U7(-5.08,-20.32) U8(-2.54,-20.32) U9(0,-20.32) U10(2.54,-20.32) U11(5.08,-20.32) U12(7.62,-20.32) U13(10.16,-20.32) U14(12.7,-20.32) U15(15.24,-20.32) U16(17.78,-20.32) U17(20.32,-20.32)
Top Overlay:
  circle w0.25: c-23.25,20.32 r0.125
  lines w0.2: -22.6,-22.6 -22.6,21.6 -21.6,22.6 22.6,22.6 22.6,-22.6 -22.6,-22.6

## PGA45X45-P208 [mm]
pads (208):
  rect 1.5x1.5 hole 0.9: A1(-20.32,20.32)
  round 1.5 hole 0.9: A2(-17.78,20.32) A3(-15.24,20.32) A4(-12.7,20.32) A5(-10.16,20.32) A6(-7.62,20.32) A7(-5.08,20.32) A8(-2.54,20.32) A9(0,20.32) A10(2.54,20.32) A11(5.08,20.32) A12(7.62,20.32) A13(10.16,20.32) A14(12.7,20.32) A15(15.24,20.32) A16(17.78,20.32) A17(20.32,20.32) B1(-20.32,17.78) B2(-17.78,17.78) B3(-15.24,17.78) B4(-12.7,17.78) B5(-10.16,17.78) B6(-7.62,17.78) B7(-5.08,17.78) B8(-2.54,17.78) B9(0,17.78) B10(2.54,17.78) B11(5.08,17.78) B12(7.62,17.78) B13(10.16,17.78) B14(12.7,17.78) B15(15.24,17.78) B16(17.78,17.78) B17(20.32,17.78) C1(-20.32,15.24) C2(-17.78,15.24) C3(-15.24,15.24) C4(-12.7,15.24) C5(-10.16,15.24) C6(-7.62,15.24) C7(-5.08,15.24) C8(-2.54,15.24) C9(0,15.24) C10(2.54,15.24) C11(5.08,15.24) C12(7.62,15.24) C13(10.16,15.24) C14(12.7,15.24) C15(15.24,15.24) C16(17.78,15.24) C17(20.32,15.24) D1(-20.32,12.7) D2(-17.78,12.7) D3(-15.24,12.7) D4(-12.7,12.7) D5(-10.16,12.7) D6(-7.62,12.7) D7(-5.08,12.7) D8(-2.54,12.7) D9(0,12.7) D10(2.54,12.7) D11(5.08,12.7) D12(7.62,12.7) D13(10.16,12.7) D14(12.7,12.7) D15(15.24,12.7) D16(17.78,12.7) D17(20.32,12.7) E1(-20.32,10.16) E2(-17.78,10.16) E3(-15.24,10.16) E4(-12.7,10.16) E14(12.7,10.16) E15(15.24,10.16) E16(17.78,10.16) E17(20.32,10.16) F1(-20.32,7.62) F2(-17.78,7.62) F3(-15.24,7.62) F4(-12.7,7.62) F14(12.7,7.62) F15(15.24,7.62) F16(17.78,7.62) F17(20.32,7.62) G1(-20.32,5.08) G2(-17.78,5.08) G3(-15.24,5.08) G4(-12.7,5.08) G14(12.7,5.08) G15(15.24,5.08) G16(17.78,5.08) G17(20.32,5.08) H1(-20.32,2.54) H2(-17.78,2.54) H3(-15.24,2.54) H4(-12.7,2.54) H14(12.7,2.54) H15(15.24,2.54) H16(17.78,2.54) H17(20.32,2.54) J1(-20.32,0) J2(-17.78,0) J3(-15.24,0) J4(-12.7,0) J14(12.7,0) J15(15.24,0) J16(17.78,0) J17(20.32,0) K1(-20.32,-2.54) K2(-17.78,-2.54) K3(-15.24,-2.54) K4(-12.7,-2.54) K14(12.7,-2.54) K15(15.24,-2.54) K16(17.78,-2.54) K17(20.32,-2.54) L1(-20.32,-5.08) L2(-17.78,-5.08) L3(-15.24,-5.08) L4(-12.7,-5.08) L14(12.7,-5.08) L15(15.24,-5.08) L16(17.78,-5.08) L17(20.32,-5.08) M1(-20.32,-7.62) M2(-17.78,-7.62) M3(-15.24,-7.62) M4(-12.7,-7.62) M14(12.7,-7.62) M15(15.24,-7.62) M16(17.78,-7.62) M17(20.32,-7.62) N1(-20.32,-10.16) N2(-17.78,-10.16) N3(-15.24,-10.16) N4(-12.7,-10.16) N14(12.7,-10.16) N15(15.24,-10.16) N16(17.78,-10.16) N17(20.32,-10.16) P1(-20.32,-12.7) P2(-17.78,-12.7) P3(-15.24,-12.7) P4(-12.7,-12.7) P5(-10.16,-12.7) P6(-7.62,-12.7) P7(-5.08,-12.7) P8(-2.54,-12.7) P9(0,-12.7) P10(2.54,-12.7) P11(5.08,-12.7) P12(7.62,-12.7) P13(10.16,-12.7) P14(12.7,-12.7) P15(15.24,-12.7) P16(17.78,-12.7) P17(20.32,-12.7) R1(-20.32,-15.24) R2(-17.78,-15.24) R3(-15.24,-15.24) R4(-12.7,-15.24) R5(-10.16,-15.24) R6(-7.62,-15.24) R7(-5.08,-15.24) R8(-2.54,-15.24) R9(0,-15.24) R10(2.54,-15.24) R11(5.08,-15.24) R12(7.62,-15.24) R13(10.16,-15.24) R14(12.7,-15.24) R15(15.24,-15.24) R16(17.78,-15.24) R17(20.32,-15.24) S1(-20.32,-17.78) S2(-17.78,-17.78) S3(-15.24,-17.78) S4(-12.7,-17.78) S5(-10.16,-17.78) S6(-7.62,-17.78) S7(-5.08,-17.78) S8(-2.54,-17.78) S9(0,-17.78) S10(2.54,-17.78) S11(5.08,-17.78) S12(7.62,-17.78) S13(10.16,-17.78) S14(12.7,-17.78) S15(15.24,-17.78) S16(17.78,-17.78) S17(20.32,-17.78) T1(-20.32,-20.32) T2(-17.78,-20.32) T3(-15.24,-20.32) T4(-12.7,-20.32) T5(-10.16,-20.32) T6(-7.62,-20.32) T7(-5.08,-20.32) T8(-2.54,-20.32) T9(0,-20.32) T10(2.54,-20.32) T11(5.08,-20.32) T12(7.62,-20.32) T13(10.16,-20.32) T14(12.7,-20.32) T15(15.24,-20.32) T16(17.78,-20.32) T17(20.32,-20.32)
Top Overlay:
  circle w0.25: c-23.35,20.32 r0.125
  lines w0.2: -22.7,-22.7 22.7,-22.7 22.7,22.7 -21.7,22.7 -22.7,21.7 -22.7,-22.7

## PGA45X45-P232 [mm]
pads (232):
  rect 1.5x1.5 hole 0.9: A1(-20.32,20.32)
  round 1.5 hole 0.9: A2(-17.78,20.32) A3(-15.24,20.32) A4(-12.7,20.32) A5(-10.16,20.32) A6(-7.62,20.32) A7(-5.08,20.32) A8(-2.54,20.32) A9(0,20.32) A10(2.54,20.32) A11(5.08,20.32) A12(7.62,20.32) A13(10.16,20.32) A14(12.7,20.32) A15(15.24,20.32) A16(17.78,20.32) A17(20.32,20.32) B1(-20.32,17.78) B2(-17.78,17.78) B3(-15.24,17.78) B4(-12.7,17.78) B5(-10.16,17.78) B6(-7.62,17.78) B7(-5.08,17.78) B8(-2.54,17.78) B9(0,17.78) B10(2.54,17.78) B11(5.08,17.78) B12(7.62,17.78) B13(10.16,17.78) B14(12.7,17.78) B15(15.24,17.78) B16(17.78,17.78) B17(20.32,17.78) C1(-20.32,15.24) C2(-17.78,15.24) C3(-15.24,15.24) C4(-12.7,15.24) C5(-10.16,15.24) C6(-7.62,15.24) C7(-5.08,15.24) C8(-2.54,15.24) C9(0,15.24) C10(2.54,15.24) C11(5.08,15.24) C12(7.62,15.24) C13(10.16,15.24) C14(12.7,15.24) C15(15.24,15.24) C16(17.78,15.24) C17(20.32,15.24) D1(-20.32,12.7) D2(-17.78,12.7) D3(-15.24,12.7) D4(-12.7,12.7) D5(-10.16,12.7) D6(-7.62,12.7) D7(-5.08,12.7) D8(-2.54,12.7) D9(0,12.7) D10(2.54,12.7) D11(5.08,12.7) D12(7.62,12.7) D13(10.16,12.7) D14(12.7,12.7) D15(15.24,12.7) D16(17.78,12.7) D17(20.32,12.7) E1(-20.32,10.16) E2(-17.78,10.16) E3(-15.24,10.16) E4(-12.7,10.16) E7(-5.08,10.16) E8(-2.54,10.16) E9(0,10.16) E10(2.54,10.16) E11(5.08,10.16) E14(12.7,10.16) E15(15.24,10.16) E16(17.78,10.16) E17(20.32,10.16) F1(-20.32,7.62) F2(-17.78,7.62) F3(-15.24,7.62) F4(-12.7,7.62) F5(-10.16,7.62) F13(10.16,7.62) F14(12.7,7.62) F15(15.24,7.62) F16(17.78,7.62) F17(20.32,7.62) G1(-20.32,5.08) G2(-17.78,5.08) G3(-15.24,5.08) G4(-12.7,5.08) G5(-10.16,5.08) G13(10.16,5.08) G14(12.7,5.08) G15(15.24,5.08) G16(17.78,5.08) G17(20.32,5.08) H1(-20.32,2.54) H2(-17.78,2.54) H3(-15.24,2.54) H4(-12.7,2.54) H5(-10.16,2.54) H13(10.16,2.54) H14(12.7,2.54) H15(15.24,2.54) H16(17.78,2.54) H17(20.32,2.54) J1(-20.32,0) J2(-17.78,0) J3(-15.24,0) J4(-12.7,0) J5(-10.16,0) J13(10.16,0) J14(12.7,0) J15(15.24,0) J16(17.78,0) J17(20.32,0) K1(-20.32,-2.54) K2(-17.78,-2.54) K3(-15.24,-2.54) K4(-12.7,-2.54) K5(-10.16,-2.54) K13(10.16,-2.54) K14(12.7,-2.54) K15(15.24,-2.54) K16(17.78,-2.54) K17(20.32,-2.54) L1(-20.32,-5.08) L2(-17.78,-5.08) L3(-15.24,-5.08) L4(-12.7,-5.08) L5(-10.16,-5.08) L13(10.16,-5.08) L14(12.7,-5.08) L15(15.24,-5.08) L16(17.78,-5.08) L17(20.32,-5.08) M1(-20.32,-7.62) M2(-17.78,-7.62) M3(-15.24,-7.62) M4(-12.7,-7.62) M5(-10.16,-7.62) M13(10.16,-7.62) M14(12.7,-7.62) M15(15.24,-7.62) M16(17.78,-7.62) M17(20.32,-7.62) N1(-20.32,-10.16) N2(-17.78,-10.16) N3(-15.24,-10.16) N4(-12.7,-10.16) N7(-5.08,-10.16) N8(-2.54,-10.16) N9(0,-10.16) N10(2.54,-10.16) N11(5.08,-10.16) N14(12.7,-10.16) N15(15.24,-10.16) N16(17.78,-10.16) N17(20.32,-10.16) P1(-20.32,-12.7) P2(-17.78,-12.7) P3(-15.24,-12.7) P4(-12.7,-12.7) P5(-10.16,-12.7) P6(-7.62,-12.7) P7(-5.08,-12.7) P8(-2.54,-12.7) P9(0,-12.7) P10(2.54,-12.7) P11(5.08,-12.7) P12(7.62,-12.7) P13(10.16,-12.7) P14(12.7,-12.7) P15(15.24,-12.7) P16(17.78,-12.7) P17(20.32,-12.7) R1(-20.32,-15.24) R2(-17.78,-15.24) R3(-15.24,-15.24) R4(-12.7,-15.24) R5(-10.16,-15.24) R6(-7.62,-15.24) R7(-5.08,-15.24) R8(-2.54,-15.24) R9(0,-15.24) R10(2.54,-15.24) R11(5.08,-15.24) R12(7.62,-15.24) R13(10.16,-15.24) R14(12.7,-15.24) R15(15.24,-15.24) R16(17.78,-15.24) R17(20.32,-15.24) T1(-20.32,-17.78) T2(-17.78,-17.78) T3(-15.24,-17.78) T4(-12.7,-17.78) T5(-10.16,-17.78) T6(-7.62,-17.78) T7(-5.08,-17.78) T8(-2.54,-17.78) T9(0,-17.78) T10(2.54,-17.78) T11(5.08,-17.78) T12(7.62,-17.78) T13(10.16,-17.78) T14(12.7,-17.78) T15(15.24,-17.78) T16(17.78,-17.78) T17(20.32,-17.78) U1(-20.32,-20.32) U2(-17.78,-20.32) U3(-15.24,-20.32) U4(-12.7,-20.32) U5(-10.16,-20.32) U6(-7.62,-20.32) U7(-5.08,-20.32) U8(-2.54,-20.32) U9(0,-20.32) U10(2.54,-20.32) U11(5.08,-20.32) U12(7.62,-20.32) U13(10.16,-20.32) U14(12.7,-20.32) U15(15.24,-20.32) U16(17.78,-20.32) U17(20.32,-20.32)
Top Overlay:
  circle w0.25: c-23.25,20.32 r0.125
  lines w0.2: -22.6,-22.6 -22.6,21.6 -21.6,22.6 22.6,22.6 22.6,-22.6 -22.6,-22.6

## PGA47X47-P191 [mm]
pads (191):
  round 1.5 hole 0.9: A2(-19.05,21.59) A3(-16.51,21.59) A4(-13.97,21.59) A5(-11.43,21.59) A6(-8.89,21.59) A7(-6.35,21.59) A8(-3.81,21.59) A9(-1.27,21.59) A10(1.27,21.59) A11(3.81,21.59) A12(6.35,21.59) A13(8.89,21.59) A14(11.43,21.59) A15(13.97,21.59) A16(16.51,21.59) A17(19.05,21.59) A18(21.59,21.59) B1(-21.59,19.05) B2(-19.05,19.05) B3(-16.51,19.05) B4(-13.97,19.05) B5(-11.43,19.05) B6(-8.89,19.05) B7(-6.35,19.05) B8(-3.81,19.05) B9(-1.27,19.05) B10(1.27,19.05) B11(3.81,19.05) B12(6.35,19.05) B13(8.89,19.05) B14(11.43,19.05) B15(13.97,19.05) B16(16.51,19.05) B17(19.05,19.05) B18(21.59,19.05) C1(-21.59,16.51) C2(-19.05,16.51) C3(-16.51,16.51) C4(-13.97,16.51) C5(-11.43,16.51) C6(-8.89,16.51) C7(-6.35,16.51) C8(-3.81,16.51) C9(-1.27,16.51) C10(1.27,16.51) C11(3.81,16.51) C12(6.35,16.51) C13(8.89,16.51) C14(11.43,16.51) C15(13.97,16.51) C16(16.51,16.51) C17(19.05,16.51) C18(21.59,16.51) D1(-21.59,13.97) D2(-19.05,13.97) D3(-16.51,13.97) D4(-13.97,13.97) D9(-1.27,13.97) D10(1.27,13.97) D15(13.97,13.97) D16(16.51,13.97) D17(19.05,13.97) D18(21.59,13.97) E1(-21.59,11.43) E2(-19.05,11.43) E3(-16.51,11.43) E16(16.51,11.43) E17(19.05,11.43) E18(21.59,11.43) F1(-21.59,8.89) F2(-19.05,8.89) F3(-16.51,8.89) F16(16.51,8.89) F17(19.05,8.89) F18(21.59,8.89) G1(-21.59,6.35) G2(-19.05,6.35) G3(-16.51,6.35) G16(16.51,6.35) G17(19.05,6.35) G18(21.59,6.35) H1(-21.59,3.81) H2(-19.05,3.81) H3(-16.51,3.81) H16(16.51,3.81) H17(19.05,3.81) H18(21.59,3.81) J1(-21.59,1.27) J2(-19.05,1.27) J3(-16.51,1.27) J4(-13.97,1.27) J15(13.97,1.27) J16(16.51,1.27) J17(19.05,1.27) J18(21.59,1.27) K1(-21.59,-1.27) K2(-19.05,-1.27) K3(-16.51,-1.27) K4(-13.97,-1.27) K15(13.97,-1.27) K16(16.51,-1.27) K17(19.05,-1.27) K18(21.59,-1.27) L1(-21.59,-3.81) L2(-19.05,-3.81) L3(-16.51,-3.81) L16(16.51,-3.81) L17(19.05,-3.81) L18(21.59,-3.81) M1(-21.59,-6.35) M2(-19.05,-6.35) M3(-16.51,-6.35) M16(16.51,-6.35) M17(19.05,-6.35) M18(21.59,-6.35) N1(-21.59,-8.89) N2(-19.05,-8.89) N3(-16.51,-8.89) N16(16.51,-8.89) N17(19.05,-8.89) N18(21.59,-8.89) P1(-21.59,-11.43) P2(-19.05,-11.43) P3(-16.51,-11.43) P16(16.51,-11.43) P17(19.05,-11.43) P18(21.59,-11.43) R1(-21.59,-13.97) R2(-19.05,-13.97) R3(-16.51,-13.97) R4(-13.97,-13.97) R9(-1.27,-13.97) R10(1.27,-13.97) R15(13.97,-13.97) R16(16.51,-13.97) R17(19.05,-13.97) R18(21.59,-13.97) T1(-21.59,-16.51) T2(-19.05,-16.51) T3(-16.51,-16.51) T4(-13.97,-16.51) T5(-11.43,-16.51) T6(-8.89,-16.51) T7(-6.35,-16.51) T8(-3.81,-16.51) T9(-1.27,-16.51) T10(1.27,-16.51) T11(3.81,-16.51) T12(6.35,-16.51) T13(8.89,-16.51) T14(11.43,-16.51) T15(13.97,-16.51) T16(16.51,-16.51) T17(19.05,-16.51) T18(21.59,-16.51) U1(-21.59,-19.05) U2(-19.05,-19.05) U3(-16.51,-19.05) U4(-13.97,-19.05) U5(-11.43,-19.05) U6(-8.89,-19.05) U7(-6.35,-19.05) U8(-3.81,-19.05) U9(-1.27,-19.05) U10(1.27,-19.05) U11(3.81,-19.05) U12(6.35,-19.05) U13(8.89,-19.05) U14(11.43,-19.05) U15(13.97,-19.05) U16(16.51,-19.05) U17(19.05,-19.05) U18(21.59,-19.05) V1(-21.59,-21.59) V2(-19.05,-21.59) V3(-16.51,-21.59) V4(-13.97,-21.59) V5(-11.43,-21.59) V6(-8.89,-21.59) V7(-6.35,-21.59) V8(-3.81,-21.59) V9(-1.27,-21.59) V10(1.27,-21.59) V11(3.81,-21.59) V12(6.35,-21.59) V13(8.89,-21.59) V14(11.43,-21.59) V15(13.97,-21.59) V16(16.51,-21.59) V17(19.05,-21.59) V18(21.59,-21.59)
Top Overlay:
  circle w0.25: c-24.55,21.59 r0.125
  lines w0.2: -23.9,-23.9 -23.9,22.9 -22.9,23.9 23.9,23.9 23.9,-23.9 -23.9,-23.9

## PGA47X47-P223 [mm]
pads (223):
  round 1.5 hole 0.9: A2(-19.05,21.59) A3(-16.51,21.59) A4(-13.97,21.59) A5(-11.43,21.59) A6(-8.89,21.59) A7(-6.35,21.59) A8(-3.81,21.59) A9(-1.27,21.59) A10(1.27,21.59) A11(3.81,21.59) A12(6.35,21.59) A13(8.89,21.59) A14(11.43,21.59) A15(13.97,21.59) A16(16.51,21.59) A17(19.05,21.59) A18(21.59,21.59) B1(-21.59,19.05) B2(-19.05,19.05) B3(-16.51,19.05) B4(-13.97,19.05) B5(-11.43,19.05) B6(-8.89,19.05) B7(-6.35,19.05) B8(-3.81,19.05) B9(-1.27,19.05) B10(1.27,19.05) B11(3.81,19.05) B12(6.35,19.05) B13(8.89,19.05) B14(11.43,19.05) B15(13.97,19.05) B16(16.51,19.05) B17(19.05,19.05) B18(21.59,19.05) C1(-21.59,16.51) C2(-19.05,16.51) C3(-16.51,16.51) C4(-13.97,16.51) C5(-11.43,16.51) C6(-8.89,16.51) C7(-6.35,16.51) C8(-3.81,16.51) C9(-1.27,16.51) C10(1.27,16.51) C11(3.81,16.51) C12(6.35,16.51) C13(8.89,16.51) C14(11.43,16.51) C15(13.97,16.51) C16(16.51,16.51) C17(19.05,16.51) C18(21.59,16.51) D1(-21.59,13.97) D2(-19.05,13.97) D3(-16.51,13.97) D4(-13.97,13.97) D5(-11.43,13.97) D6(-8.89,13.97) D7(-6.35,13.97) D8(-3.81,13.97) D9(-1.27,13.97) D10(1.27,13.97) D11(3.81,13.97) D12(6.35,13.97) D13(8.89,13.97) D14(11.43,13.97) D15(13.97,13.97) D16(16.51,13.97) D17(19.05,13.97) D18(21.59,13.97) E1(-21.59,11.43) E2(-19.05,11.43) E3(-16.51,11.43) E4(-13.97,11.43) E15(13.97,11.43) E16(16.51,11.43) E17(19.05,11.43) E18(21.59,11.43) F1(-21.59,8.89) F2(-19.05,8.89) F3(-16.51,8.89) F4(-13.97,8.89) F15(13.97,8.89) F16(16.51,8.89) F17(19.05,8.89) F18(21.59,8.89) G1(-21.59,6.35) G2(-19.05,6.35) G3(-16.51,6.35) G4(-13.97,6.35) G15(13.97,6.35) G16(16.51,6.35) G17(19.05,6.35) G18(21.59,6.35) H1(-21.59,3.81) H2(-19.05,3.81) H3(-16.51,3.81) H4(-13.97,3.81) H15(13.97,3.81) H16(16.51,3.81) H17(19.05,3.81) H18(21.59,3.81) J1(-21.59,1.27) J2(-19.05,1.27) J3(-16.51,1.27) J4(-13.97,1.27) J15(13.97,1.27) J16(16.51,1.27) J17(19.05,1.27) J18(21.59,1.27) K1(-21.59,-1.27) K2(-19.05,-1.27) K3(-16.51,-1.27) K4(-13.97,-1.27) K15(13.97,-1.27) K16(16.51,-1.27) K17(19.05,-1.27) K18(21.59,-1.27) L1(-21.59,-3.81) L2(-19.05,-3.81) L3(-16.51,-3.81) L4(-13.97,-3.81) L15(13.97,-3.81) L16(16.51,-3.81) L17(19.05,-3.81) L18(21.59,-3.81) M1(-21.59,-6.35) M2(-19.05,-6.35) M3(-16.51,-6.35) M4(-13.97,-6.35) M15(13.97,-6.35) M16(16.51,-6.35) M17(19.05,-6.35) M18(21.59,-6.35) N1(-21.59,-8.89) N2(-19.05,-8.89) N3(-16.51,-8.89) N4(-13.97,-8.89) N15(13.97,-8.89) N16(16.51,-8.89) N17(19.05,-8.89) N18(21.59,-8.89) P1(-21.59,-11.43) P2(-19.05,-11.43) P3(-16.51,-11.43) P4(-13.97,-11.43) P15(13.97,-11.43) P16(16.51,-11.43) P17(19.05,-11.43) P18(21.59,-11.43) R1(-21.59,-13.97) R2(-19.05,-13.97) R3(-16.51,-13.97) R4(-13.97,-13.97) R5(-11.43,-13.97) R6(-8.89,-13.97) R7(-6.35,-13.97) R8(-3.81,-13.97) R9(-1.27,-13.97) R10(1.27,-13.97) R11(3.81,-13.97) R12(6.35,-13.97) R13(8.89,-13.97) R14(11.43,-13.97) R15(13.97,-13.97) R16(16.51,-13.97) R17(19.05,-13.97) R18(21.59,-13.97) T1(-21.59,-16.51) T2(-19.05,-16.51) T3(-16.51,-16.51) T4(-13.97,-16.51) T5(-11.43,-16.51) T6(-8.89,-16.51) T7(-6.35,-16.51) T8(-3.81,-16.51) T9(-1.27,-16.51) T10(1.27,-16.51) T11(3.81,-16.51) T12(6.35,-16.51) T13(8.89,-16.51) T14(11.43,-16.51) T15(13.97,-16.51) T16(16.51,-16.51) T17(19.05,-16.51) T18(21.59,-16.51) U1(-21.59,-19.05) U2(-19.05,-19.05) U3(-16.51,-19.05) U4(-13.97,-19.05) U5(-11.43,-19.05) U6(-8.89,-19.05) U7(-6.35,-19.05) U8(-3.81,-19.05) U9(-1.27,-19.05) U10(1.27,-19.05) U11(3.81,-19.05) U12(6.35,-19.05) U13(8.89,-19.05) U14(11.43,-19.05) U15(13.97,-19.05) U16(16.51,-19.05) U17(19.05,-19.05) U18(21.59,-19.05) V1(-21.59,-21.59) V2(-19.05,-21.59) V3(-16.51,-21.59) V4(-13.97,-21.59) V5(-11.43,-21.59) V6(-8.89,-21.59) V7(-6.35,-21.59) V8(-3.81,-21.59) V9(-1.27,-21.59) V10(1.27,-21.59) V11(3.81,-21.59) V12(6.35,-21.59) V13(8.89,-21.59) V14(11.43,-21.59) V15(13.97,-21.59) V16(16.51,-21.59) V17(19.05,-21.59) V18(21.59,-21.59)
Top Overlay:
  circle w0.25: c-24.55,21.59 r0.125
  lines w0.2: -23.9,-23.9 23.9,-23.9 23.9,23.9 -22.9,23.9 -23.9,22.9 -23.9,-23.9

## PGA47X47-P305 [mm]
pads (305):
  round 1.4 hole 0.8: A5(-16.51,21.59) A7(-13.97,21.59) A9(-11.43,21.59) A11(-8.89,21.59) A13(-6.35,21.59) A15(-3.81,21.59) A17(-1.27,21.59) A19(1.27,21.59) A21(3.81,21.59) A23(6.35,21.59) A25(8.89,21.59) A27(11.43,21.59) A29(13.97,21.59) A31(16.51,21.59) AA1(-21.59,-3.81) AA3(-19.05,-3.81) AA5(-16.51,-3.81) AA31(16.51,-3.81) AA33(19.05,-3.81) AA35(21.59,-3.81) AB2(-20.32,-5.08) AB4(-17.78,-5.08) AB32(17.78,-5.08) AB34(20.32,-5.08) AC1(-21.59,-6.35) AC3(-19.05,-6.35) AC5(-16.51,-6.35) AC31(16.51,-6.35) AC33(19.05,-6.35) AC35(21.59,-6.35) AD2(-20.32,-7.62) AD4(-17.78,-7.62) AD32(17.78,-7.62) AD34(20.32,-7.62) AE1(-21.59,-8.89) AE3(-19.05,-8.89) AE5(-16.51,-8.89) AE31(16.51,-8.89) AE33(19.05,-8.89) AE35(21.59,-8.89) AF2(-20.32,-10.16) AF4(-17.78,-10.16) AF32(17.78,-10.16) AF34(20.32,-10.16) AG1(-21.59,-11.43) AG3(-19.05,-11.43) AG5(-16.51,-11.43) AG31(16.51,-11.43) AG33(19.05,-11.43) AG35(21.59,-11.43) AH2(-20.32,-12.7) AH4(-17.78,-12.7) AH32(17.78,-12.7) AH34(20.32,-12.7) AJ1(-21.59,-13.97) AJ3(-19.05,-13.97) AJ5(-16.51,-13.97) AJ31(16.51,-13.97) AJ33(19.05,-13.97) AJ35(21.59,-13.97) AK2(-20.32,-15.24) AK4(-17.78,-15.24) AK8(-12.7,-15.24) AK10(-10.16,-15.24) AK12(-7.62,-15.24) AK14(-5.08,-15.24) AK16(-2.54,-15.24) AK18(0,-15.24) AK20(2.54,-15.24) AK22(5.08,-15.24) AK24(7.62,-15.24) AK26(10.16,-15.24) AK28(12.7,-15.24) AK32(17.78,-15.24) AK34(20.32,-15.24) AL1(-21.59,-16.51) AL3(-19.05,-16.51) AL5(-16.51,-16.51) AL7(-13.97,-16.51) AL9(-11.43,-16.51) AL11(-8.89,-16.51) AL13(-6.35,-16.51) AL15(-3.81,-16.51) AL17(-1.27,-16.51) AL19(1.27,-16.51) AL21(3.81,-16.51) AL23(6.35,-16.51) AL25(8.89,-16.51) AL27(11.43,-16.51) AL29(13.97,-16.51) AL31(16.51,-16.51) AL33(19.05,-16.51) AL35(21.59,-16.51) AM2(-20.32,-17.78) AM4(-17.78,-17.78) AM6(-15.24,-17.78) AM8(-12.7,-17.78) AM10(-10.16,-17.78) AM12(-7.62,-17.78) AM14(-5.08,-17.78) AM16(-2.54,-17.78) AM18(0,-17.78) AM20(2.54,-17.78) AM22(5.08,-17.78) AM24(7.62,-17.78) AM26(10.16,-17.78) AM28(12.7,-17.78) AM30(15.24,-17.78) AM32(17.78,-17.78) AM34(20.32,-17.78) AN5(-16.51,-19.05) AN7(-13.97,-19.05) AN9(-11.43,-19.05) AN11(-8.89,-19.05) AN13(-6.35,-19.05) AN15(-3.81,-19.05) AN17(-1.27,-19.05) AN19(1.27,-19.05) AN21(3.81,-19.05) AN23(6.35,-19.05) AN25(8.89,-19.05) AN27(11.43,-19.05) AN29(13.97,-19.05) AN31(16.51,-19.05) AN33(19.05,-19.05) AP4(-17.78,-20.32) AP6(-15.24,-20.32) AP8(-12.7,-20.32) AP10(-10.16,-20.32) AP12(-7.62,-20.32) AP14(-5.08,-20.32) AP16(-2.54,-20.32) AP18(0,-20.32) AP20(2.54,-20.32) AP22(5.08,-20.32) AP24(7.62,-20.32) AP26(10.16,-20.32) AP28(12.7,-20.32) AP30(15.24,-20.32) AP32(17.78,-20.32) AR5(-16.51,-21.59) AR7(-13.97,-21.59) AR9(-11.43,-21.59) AR11(-8.89,-21.59) AR13(-6.35,-21.59) AR15(-3.81,-21.59) AR17(-1.27,-21.59) AR19(1.27,-21.59) AR21(3.81,-21.59) AR23(6.35,-21.59) AR25(8.89,-21.59) AR27(11.43,-21.59) AR29(13.97,-21.59) AR31(16.51,-21.59) B2(-20.32,20.32) B4(-17.78,20.32) B6(-15.24,20.32) B8(-12.7,20.32) B10(-10.16,20.32) B12(-7.62,20.32) B14(-5.08,20.32) B16(-2.54,20.32) B18(0,20.32) B20(2.54,20.32) B22(5.08,20.32) B24(7.62,20.32) B26(10.16,20.32) B28(12.7,20.32) B30(15.24,20.32) B32(17.78,20.32) C3(-19.05,19.05) C5(-16.51,19.05) C7(-13.97,19.05) C9(-11.43,19.05) C11(-8.89,19.05) C13(-6.35,19.05) C15(-3.81,19.05) C17(-1.27,19.05) C19(1.27,19.05) C21(3.81,19.05) C23(6.35,19.05) C25(8.89,19.05) C27(11.43,19.05) C29(13.97,19.05) C31(16.51,19.05) D2(-20.32,17.78) D4(-17.78,17.78) D6(-15.24,17.78) D8(-12.7,17.78) D10(-10.16,17.78) D12(-7.62,17.78) D14(-5.08,17.78) D16(-2.54,17.78) D18(0,17.78) D20(2.54,17.78) D22(5.08,17.78) D24(7.62,17.78) D26(10.16,17.78) D28(12.7,17.78) D30(15.24,17.78) D32(17.78,17.78) D34(20.32,17.78) E1(-21.59,16.51) E3(-19.05,16.51) E5(-16.51,16.51) E7(-13.97,16.51) E9(-11.43,16.51) E11(-8.89,16.51) E13(-6.35,16.51) E15(-3.81,16.51) E17(-1.27,16.51) E19(1.27,16.51) E21(3.81,16.51) E23(6.35,16.51) E25(8.89,16.51) E27(11.43,16.51) E29(13.97,16.51) E31(16.51,16.51) E33(19.05,16.51) E35(21.59,16.51) F2(-20.32,15.24) F4(-17.78,15.24) F8(-12.7,15.24) F10(-10.16,15.24) F12(-7.62,15.24) F14(-5.08,15.24) F16(-2.54,15.24) F18(0,15.24) F20(2.54,15.24) F22(5.08,15.24) F24(7.62,15.24) F26(10.16,15.24) F28(12.7,15.24) F32(17.78,15.24) F34(20.32,15.24) G1(-21.59,13.97) G3(-19.05,13.97) G5(-16.51,13.97) G31(16.51,13.97) G33(19.05,13.97) G35(21.59,13.97) H2(-20.32,12.7) H4(-17.78,12.7) H32(17.78,12.7) H34(20.32,12.7) J1(-21.59,11.43) J3(-19.05,11.43) J5(-16.51,11.43) J31(16.51,11.43) J33(19.05,11.43) J35(21.59,11.43) K2(-20.32,10.16) K4(-17.78,10.16) K32(17.78,10.16) K34(20.32,10.16) L1(-21.59,8.89) L3(-19.05,8.89) L5(-16.51,8.89) L31(16.51,8.89) L33(19.05,8.89) L35(21.59,8.89) M2(-20.32,7.62) M4(-17.78,7.62) M32(17.78,7.62) M34(20.32,7.62) N1(-21.59,6.35) N3(-19.05,6.35) N5(-16.51,6.35) N31(16.51,6.35) N33(19.05,6.35) N35(21.59,6.35) P2(-20.32,5.08) P4(-17.78,5.08) P32(17.78,5.08) P34(20.32,5.08) R1(-21.59,3.81) R3(-19.05,3.81) R5(-16.51,3.81) R31(16.51,3.81) R33(19.05,3.81) R35(21.59,3.81) T2(-20.32,2.54) T4(-17.78,2.54) T32(17.78,2.54) T34(20.32,2.54) U1(-21.59,1.27) U3(-19.05,1.27) U5(-16.51,1.27) U31(16.51,1.27) U33(19.05,1.27) U35(21.59,1.27) V2(-20.32,0) V4(-17.78,0) V32(17.78,0) V34(20.32,0) W1(-21.59,-1.27) W3(-19.05,-1.27) W5(-16.51,-1.27) W31(16.51,-1.27) W33(19.05,-1.27) W35(21.59,-1.27) Y2(-20.32,-2.54) Y4(-17.78,-2.54) Y32(17.78,-2.54) Y34(20.32,-2.54)
Top Overlay:
  circle w0.25: c-23.51,21.59 r0.125
  lines w0.2: -22.86,-22.86 -22.86,21.86 -21.86,22.86 22.86,22.86 22.86,-22.86 -22.86,-22.86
